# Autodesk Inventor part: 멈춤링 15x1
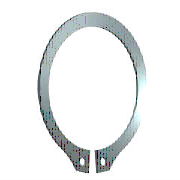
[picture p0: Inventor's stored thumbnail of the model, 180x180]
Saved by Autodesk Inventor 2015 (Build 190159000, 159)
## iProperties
Created: 2015-09
Part Number: 멈춤링 15x1
Material: 강철, 연강
Description: 리테이닝 링(C형)
Document SubType Name: Modeling
Standard: KS B 1336
Designer: mm
Standards Organization: KS
Language: ko-KR
Size Designation: 15 x 1
Categories: <MemberInstance><Categories><Category DisplayName="샤프트 부품" InternalName="7f7aeb1f-a693-4053-b835-cee3144e0d98" Mnemonic="SHFT"><Category DisplayName="써클립" Inter
Density: 1 g/cm^3
Appearance: 파란색 - 벽 페인트 - 광택
IsCustomPart: 1
Author: mduedu
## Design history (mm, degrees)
sketch "스케치1"
  geometry: L1 (-6, 0)-(6, 0) reference; L2 (0, 20.189)-(0, -80.536) reference; L3 (-48.09, 0)-(48.09, 0) reference; L4 (-0.425, -14.637)-(-0.425, -18.137); L5 (-0.425, -6.54)-(-0.425, -13.29); L6 (-2.795, 2.1)-(3.672, 2.1); L7 (0.425, -6.54)-(0.425, -13.29); L8 (0.425, -14.637)-(0.425, -18.137); C1 r 0.85 at (-1.7, -16.283); C2 r 0.85 at (1.7, -16.283); A1 r 7.15 centre (0, -7.5) between (0.425, -14.637) and (-0.425, -14.637); A2 r 9.075 centre (0, -6.975) between (4.291, -14.971) and (-4.291, -14.971); A3 r 10.646 centre (0, -7.5) between (-2.023, -17.952) and (-0.425, -18.137); A4 r 1.7 centre (-1.7, -16.283) between (-3.397, -16.376) and (-2.023, -17.952); A5 r 1.7 centre (-5.095, -16.469) between (-3.397, -16.376) and (-4.291, -14.971); A6 r 1.7 centre (5.095, -16.469) between (4.291, -14.971) and (3.397, -16.376); A7 r 1.7 centre (1.7, -16.283) between (2.023, -17.952) and (3.397, -16.376); A8 r 10.646 centre (0, -7.5) between (0.425, -18.137) and (2.023, -17.952)
  constraints: 16 point on circle, 12 end point, 10 centre point, 9 symmetric about line, 5 point on line, 4 tangent, 3 coincident, 2 horizontal, 1 perpendicular, 1 vertical, 5 other
  dimensions: "d0" = 14.3 diameter of A1 (= ND); "d1" = 3.5 distance of L4.end L4.start (= SRB2); "d6" = 0.425 distance between parallel lines of L2 L5 (= 0.25 x SD5); "d7" = 2.1 distance between parallel lines of L6 L3 (= SRB1); "d8" = 0.525 distance of A1.centre A2.centre (= 0.25 x SRB1); "d9" = 1.7 radius of A4 (= SD5); "d10" = 1.7 radius of A5 (= SD5); "d11" = 1.275 distance from line of L4 A4.centre (= 0.75 x SD5); "d12" = 1.7 diameter of C1 (= SD5); "d13" = 1.7 diameter of C2 (= SD5); "d14" = 7.5 distance from line of A1.centre L1 (= 0.5 x WD)
extrude "본체" new body sketch "스케치1" distance "d2" = 1 (= SD); taper "d3" = 0 deg
workaxis "Work Axis1"
workplane "Work Plane1"
body "Solid1"
other parameters: "WD" = 15 (= WDMIN) [user parameter; used in 1 equation term], "SD" = 1 [user parameter; used in 1 equation term], "SRB1" = 2.1 [user parameter; used in 2 equation terms], "ND" = 14.3 [user parameter; used in 1 equation term], "SRB2" = 3.5 [user parameter; used in 1 equation term], "SD5" = 1.7 [user parameter; used in 6 equation terms], "d15" = 0, "d16" = 0, "d17" = 0, "d41" = 0, "d42" = 0, "WDMIN" = 15 [user parameter; used in 1 equation term], "SD3" = 13.8 [user parameter], "WDMAX" = 16 [user parameter]
